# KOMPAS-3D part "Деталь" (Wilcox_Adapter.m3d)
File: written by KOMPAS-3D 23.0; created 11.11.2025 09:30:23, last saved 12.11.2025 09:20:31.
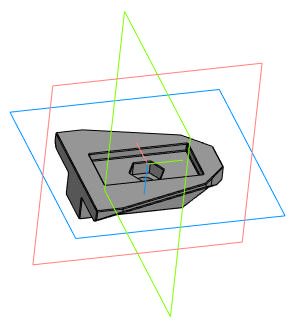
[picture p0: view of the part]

Document properties: Автор: ADMIN; Полное имя файла: D:\YandexDisk\Model\NVG\ARM mkII\Wilcox Adapter.m3d

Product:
- Part/product: Деталь
    Масса: 0.030122

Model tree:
1. Эскиз:1
2. Элемент выдавливания:1
     Расстояние 1 = 3.8
3. Эскиз:2  (with: Элемент выдавливания:1)
4. Элемент выдавливания:2
     Расстояние 1 = 6
5. Эскиз:3  (with: Элемент выдавливания:1)
6. Элемент выдавливания:3
     Расстояние 2 = 9.8
7. Эскиз:4  (with: Элемент выдавливания:1)
8. Элемент выдавливания:4
     Расстояние 2 = 2
9. Эскиз:5  (with: Элемент выдавливания:4)
10. Элемент выдавливания:5
     Расстояние 2 = 3.2
11. Фаска:1  (with: Элемент выдавливания:1)
     Угол = 45; Длина 1 = 2.9; Длина 2 = 2.9
12. Фаска:3  (with: Элемент выдавливания:2)
     Угол = 50; Длина 1 = 6; Длина 2 = 7.15052
13. Фаска:2  (with: Элемент выдавливания:1, Элемент выдавливания:2, Элемент выдавливания:4, Элемент выдавливания:3, Фаска:3)
     Угол = 45; Длина 1 = 0.2; Длина 2 = 0.2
